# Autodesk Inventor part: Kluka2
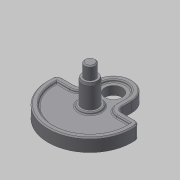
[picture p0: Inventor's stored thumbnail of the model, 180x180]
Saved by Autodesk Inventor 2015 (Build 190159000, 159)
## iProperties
Created: 2012-07
Part Number: Kluka2
Document SubType Name: Modeling
Designer: Michman
Material: Všeobecné
Density: 1 g/cm^3
Appearance: Výchozí
Author: Michman
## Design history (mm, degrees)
sketch "Náčrt1"
  geometry: L1 (16.943, 22.658)-(16.943, 13.658); L2 (-17.057, 22.658)-(-17.057, 13.658); L3 (-33.924, 8.658)-(-22.057, 8.658); L4 (21.943, 8.658)-(33.811, 8.658); C1 r 8.05 at (-0.057, 22.658); A1 r 39 centre (-0.057, 0.658) between (-38.905, 4.1) and (38.791, 4.1); A2 r 17 centre (-0.057, 22.658) between (16.943, 22.658) and (-17.057, 22.658); A3 r 5 centre (-33.924, 3.658) between (-33.924, 8.658) and (-38.905, 4.1); A4 r 5 centre (-22.057, 13.658) between (-22.057, 8.658) and (-17.057, 13.658); A5 r 5 centre (21.943, 13.658) between (16.943, 13.658) and (21.943, 8.658); A6 r 5 centre (33.811, 3.658) between (38.791, 4.1) and (33.811, 8.658)
  constraints: 12 point on circle, 9 tangent, 8 end point, 7 centre point, 3 equal radius, 2 horizontal, 2 perpendicular, 1 coincident
  dimensions: "d0" = 78 diameter of A1; "d1" = 34 diameter of A2; "d2" = 22 distance of A1.centre A2.centre; "d4" = 5 radius of A3; "d5" = 16.1 diameter of C1
extrude "Vysunutí1" new body sketch "Náčrt1" distance "d6" = 10; taper "d7" = 0 deg
chamfer "Zkosení1" distance "d8" = 1; stored, may be unused: second distance "d9" = 2, angle "d10" = 45 deg
sketch "Náčrt2"
  geometry: L1 (-37.342, 10)-(7.156, 10) reference; L2 (39.658, 0)-(39.658, 10) reference; L3 (0.658, 12.255)-(0.658, 48.902); L4 (8.158, 10)-(8.158, 38.573); L5 (8.158, 38.573)-(7.158, 44.94); L6 (7.158, 44.94)-(7.158, 54.562); L7 (7.158, 54.562)-(5.591, 86.046); L8 (5.591, 86.046)-(4.658, 86); L9 (4.658, 86)-(4.658, 97); L10 (4.658, 97)-(2.519, 97); L11 (-38.342, 0)-(-38.342, 9) reference; L12 (2.519, 97)-(0.658, 97); L13 (0.658, 48.902)-(0.658, 97); L14 (0.658, 12.255)-(0.658, 10); L15 (7.156, 10)-(8.158, 10)
  constraints: 24 end point, 6 perpendicular, 4 parallel, 2 point on line
  dimensions: "d11" = 7.5 distance between parallel lines of L4 L3; "d12" = 39 distance between parallel lines of L3 L2; "d13" = 28.57289 distance of L4.start L4.end; "d14" = 87 distance between parallel lines of L10 L1; "d15" = 76 distance from line of L1 L8.end; "d16" = 6.5 distance from line of L3 L5.end; "d17" = 2.85 deg angle of L7 L6; "d18" = 4 distance between parallel lines of L3 L9
revolve "Rotace1" sketch "Náčrt2" stored, may be unused: angle "d19" = 90 deg
feature "Závit1" dims "d20" = 10, "d21" = 0
chamfer "Zkosení2" distance "d22" = 1.2; stored, may be unused: second distance "d23" = 2, angle "d24" = 45 deg
sketch "Náčrt7"
  geometry: L1 (-5.842, 54.562)-(-5.842, 44.94) reference; L2 (-4.274, 86.046)-(5.591, 86.046) reference; C1 r 5 at (-7.542, 77.046)
  constraints: 1 centre point
  dimensions: "d37" = 10 diameter of C1; "d38" = 1.7 distance from line of L1 C1.centre; "d39" = 9 distance from line of L2 C1.centre
extrude "Vysunutí6" cut sketch "Náčrt7" stored distance "d40" = 2; taper "d41" = 0 deg
sketch "Náčrt8"
  geometry: L1 (-33.811, 8.658)-(-21.943, 8.658) reference; L2 (22.057, 8.658)-(33.924, 8.658) reference; A1 r 5 centre (-33.811, 3.658) between (-33.811, 8.658) and (-38.791, 4.1) reference; A2 r 39 centre (0.057, 0.658) between (-38.791, 4.1) and (38.905, 4.1) reference; A3 r 5 centre (33.924, 3.658) between (38.905, 4.1) and (33.924, 8.658) reference; A4 r 19.286 centre (0.057, 0.658) between (-18.79, 4.748) and (18.904, 4.748); A5 r 3.226 centre (-21.943, 5.432) between (-18.79, 4.748) and (-21.943, 8.658); A6 r 3.226 centre (22.057, 5.432) between (22.057, 8.658) and (18.904, 4.748)
  constraints: 6 point on circle, 3 centre point, 2 tangent, 1 coincident
extrude "Vysunutí7" join sketch "Náčrt8" distance "d42" = 2; taper "d43" = 0 deg
fillet "Zaoblení1" dims "d44" = 0.5
sketch "Náčrt9"
  geometry: L1 (-31.092, 103.145)-(31.099, 103.145); L2 (31.099, 103.145)-(31.099, 32); L3 (31.099, 32)-(-31.092, 32); L4 (-31.092, 32)-(-31.092, 103.145); L5 (-37.342, 10)-(7.156, 10) reference
  constraints: 8 end point, 2 parallel, 1 horizontal, 1 perpendicular
  dimensions: "d45" = 22 distance between parallel lines of L3 L5
extrude "Vysunutí8" cut sketch "Náčrt9" stored distance "d46" = 50; taper "d47" = 0 deg
chamfer "Zkosení3" distance "d48" = 2.5; stored, may be unused: second distance "d49" = 2, angle "d50" = 15 deg
sketch "Náčrt10"
  geometry: C1 r 6.83 at (0, 0) reference; C2 r 5 at (0, 0)
  constraints: 1 centre point, 1 coincident
  dimensions: "d51" = 10 diameter of C2
extrude "Vysunutí9" join sketch "Náčrt10" distance "d52" = 12; taper "d53" = 0 deg
chamfer "Zkosení4" distance "d54" = 1; stored, may be unused: second distance "d55" = 2, angle "d56" = 15 deg
fillet "Zaoblení2" dims "d57" = 1
sketch "Náčrt11"
  geometry: L1 (21.943, 7.658)-(33.811, 7.658) reference; L2 (15.943, 22.658)-(15.943, 13.658) reference; L3 (-16.057, 13.658)-(-16.057, 22.658) reference; L4 (-33.924, 7.658)-(-22.057, 7.658) reference; L5 (21.943, 3.658)-(33.811, 3.658); L6 (-33.924, 3.658)-(-22.057, 3.658); L7 (-12.057, 13.658)-(-12.057, 22.658); L8 (11.943, 22.658)-(11.943, 13.658); C1 r 8.05 at (-0.057, 22.658) reference; C2 r 7.5 at (0, 0.658) reference; C3 r 10 at (0, 0.658); C4 r 8.05 at (-0.057, 22.658); A1 r 4 centre (33.811, 3.658) between (37.795, 4.011) and (33.811, 7.658) reference; A2 r 6 centre (21.943, 13.658) between (15.943, 13.658) and (21.943, 7.658) reference; A3 r 16 centre (-0.057, 22.658) between (15.943, 22.658) and (-16.057, 22.658) reference; A4 r 6 centre (-22.057, 13.658) between (-22.057, 7.658) and (-16.057, 13.658) reference; A5 r 4 centre (-33.924, 3.658) between (-33.924, 7.658) and (-37.909, 4.011) reference; A6 r 38 centre (-0.057, 0.658) between (-37.909, 4.011) and (37.795, 4.011) reference; A7 r 10 centre (21.943, 13.658) between (11.943, 13.658) and (21.943, 3.658); A8 r 34 centre (-0.057, 0.658) between (-33.924, 3.658) and (33.811, 3.658); A9 r 0 centre (-33.924, 3.658) between (-33.924, 3.658) and (-33.924, 3.658); A10 r 10 centre (-22.057, 13.658) between (-22.057, 3.658) and (-12.057, 13.658); A11 r 12 centre (-0.057, 22.658) between (11.943, 22.658) and (-12.057, 22.658); 1 further point
  constraints: 8 end point, 8 point on circle, 7 centre point, 2 coincident, 2 coincident with centre, 1 concentric, 13 other
  dimensions: "d58" = 4 radial gap between concentric circles of A8 A6; "d59" = 20 diameter of C3
extrude "Vysunutí10" cut sketch "Náčrt11" distance "d60" = 2; taper "d61" = 0 deg
fillet "Zaoblení3" dims "d62" = 1
node "Těleso1"
node "Objemová tělesa"
node "Povrchová tělesa"
other parameters: "d3" = 8
